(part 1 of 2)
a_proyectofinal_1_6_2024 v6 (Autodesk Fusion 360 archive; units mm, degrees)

design "a_proyectofinal_1_6_2024" references "nichrome wire", "LCD_grande", "a_supeior_finaldeproyecto_2024", "_dht22 aM2302.38a1238d-d74f-4ad3-8c3c-e908f9285f82", "VENTILADOR", "acentral_unido", "acentral_unido", "base1", "soporte_vidrio", "vidrio"
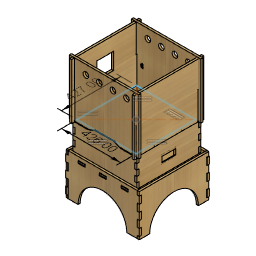
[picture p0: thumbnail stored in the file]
component_insert "Component Insert2"
component_insert "Component Insert3"
component_insert "Component Insert4"
component_insert "Component Insert5"
component_insert "Component Insert6"
position "Position1"
sketch "Sketch1" plane through (0, 0, 0) normal (0, 0, 1) x axis (1, 0, 0)
  line L1 (12, -36.5) -> (438, -36.5)
  line L2 (12, -463.5) -> (12, -36.5)
  line L3 (438, -463.5) -> (12, -463.5)
  line L4 (438, -36.5) -> (438, -463.5)
  line L5 (12, -463.5) -> (438, -36.5)
  line L6 (438, -463.5) -> (12, -36.5)
  point P6 (225, -250)
  point P4 (12, -463.5)
  point P5 (438, -463.5)
  point P3 (12, -36.5)
  horizontal L1
  perpendicular L1 L2
  parallel L1 L3
  parallel L2 L4
  coincident L5 P6
  coincident L6 P6
  dimension "d1" distance P4 P5 = 426
  dimension "d2" distance P3 P4 = 427
extrude "Extrude1" new body sketch "Sketch1" profile of L1 L2 L3 L4 along normal blind 3
sketch "Sketch2" plane through (0, 0, 3) normal (0, 0, 1) x axis (-1, 0, 0)
  line L1 (-438, 36.5) -> (-438, 463.5)
  line L2 (-12, 36.5) -> (-438, 36.5)
  line L3 (-12, 463.5) -> (-12, 36.5)
  line L4 (-438, 463.5) -> (-12, 463.5)
  circle C1 centre (-225, 250) radius 80
  dimension "d5" diameter C1 = 160
extrude "Extrude2" cut sketch "Sketch2" profile of C1 distance 5
sketch "Sketch3" plane through (0, 0, 3) normal (0, 0, 1) x axis (-1, 0, 0)
  line L1 (-438, 36.5) -> (-438, 463.5)
  line L2 (-12, 36.5) -> (-438, 36.5)
  line L3 (-12, 463.5) -> (-12, 36.5)
  line L4 (-438, 463.5) -> (-12, 463.5)
  circle C1 centre (-225, 250) radius 80
component_insert "Component Insert8"
component_insert "Component Insert9"
component_insert "Component Insert10"
component_insert "Component Insert11"
component_insert "Component Insert12"
component_insert "Component Insert13"
component_insert "Component Insert14"

design "b_superior_atras"
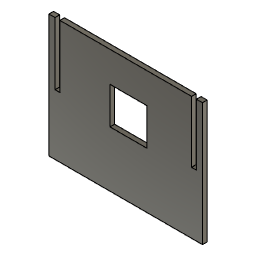
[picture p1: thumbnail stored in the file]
sketch "Sketch1" plane through (0, 0, 0) normal (0, 1, 0) x axis (1, 0, 0)
  line L1 (500, 0) -> (500, -400)
  line L2 (0, 0) -> (500, 0)
  line L3 (0, -400) -> (0, 0)
  line L4 (20, -400) -> (0, -400)
  line L5 (20, -200) -> (20, -400)
  line L6 (0, -400) -> (0, -200)
  line L7 (480, -400) -> (500, -400)
  line L8 (480, -200) -> (480, -400)
  line L9 (500, -400) -> (500, -200)
  line L10 (35.75, -196.5937) -> (35.75, -400)
  line L11 (20, -196.5937) -> (35.75, -196.5937)
  line L12 (20, -400) -> (20, -196.5937)
  line L13 (464.25, -200) -> (464.25, -400)
  line L14 (480, -200) -> (464.25, -200)
  line L15 (480, -400) -> (480, -200)
  line L16 (20, -400) -> (0, -400)
  line L17 (464.25, -400) -> (35.75, -400)
  line L18 (500, -400) -> (480, -400)
  point P2 (0, -400)
  point P3 (500, -400)
  point P5 (0, 0)
  point P6 (20, -400)
  point P8 (0, -200)
  point P9 (480, -400)
  point P11 (500, -200)
  point P12 (35.75, -400)
  point P15 (464.25, -400)
  horizontal L16
  vertical L1
  horizontal L2
  vertical L3
  horizontal L4
  vertical L5
  vertical L6
  horizontal L7
  vertical L8
  vertical L9
  vertical L10
  horizontal L11
  vertical L12
  vertical L13
  horizontal L14
  vertical L15
  collinear L16 L17
  collinear L17 L18
  dimension "d1" distance P2 P3 = 500
  dimension "d2" distance P2 P5 = 400
  dimension "d3" distance P2 P6 = 20
  dimension "d4" distance P2 P8 = 200
  dimension "d5" distance P3 P9 = 20
  dimension "d6" distance P3 P11 = 200
  dimension "d7" distance P6 P12 = 15.75
  dimension "d8" distance P9 P15 = 15.75
extrude "Extrude1" new body sketch "Sketch1" profile of L18 L1 L2 L3 L4 L5 L6 L7 L8 L9 L10 L11 L12 L13 L14 L15 along normal blind 15
sketch "Sketch2" plane through (0, 0, 0) normal (0, -1, 0) x axis (1, 0, 0)
  line L1 (35.75, 400) -> (464.25, 400)
  line L2 (35.75, 196.5937) -> (35.75, 400)
  line L3 (20, 196.5937) -> (35.75, 196.5937)
  line L4 (20, 400) -> (20, 196.5937)
  line L5 (0, 400) -> (20, 400)
  line L6 (0, 0) -> (0, 400)
  line L7 (500, 0) -> (0, 0)
  line L8 (500, 400) -> (500, 0)
  line L9 (480, 400) -> (500, 400)
  line L10 (480, 200) -> (480, 400)
  line L11 (464.25, 200) -> (480, 200)
  line L12 (464.25, 400) -> (464.25, 200)
  line L13 (318.7507, 301.2232) -> (198.7507, 301.2232)
  line L14 (318.7507, 181.2232) -> (318.7507, 301.2232)
  line L15 (198.7507, 181.2232) -> (318.7507, 181.2232)
  line L16 (198.7507, 301.2232) -> (198.7507, 181.2232)
  point P14 (198.7507, 301.2232)
  point P15 (318.7507, 301.2232)
  point P17 (198.7507, 181.2232)
  horizontal L13
  vertical L14
  horizontal L15
  vertical L16
  dimension "d12" distance P14 P15 = 120
  dimension "d13" distance P14 P17 = 120
extrude "Extrude2" cut sketch "Sketch2" profile of L13 L14 L15 L16 against normal blind 200

design "nichrome wire"
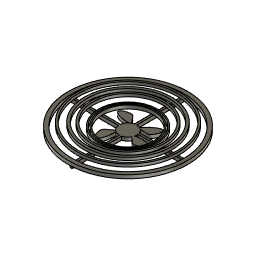
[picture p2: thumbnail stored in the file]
sketch "Sketch1" plane through (0, 0, 0) normal (0, 0, 1) x axis (1, 0, 0)
  curve K1 (6.0577, 10.9616) -> (6.0577, 10.9616)
  curve K2 (6.0577, 10.9616) -> (6.0577, 10.9616)
  curve K3 (6.0577, 10.9616) -> (6.0577, 10.9616)
  curve K4 (10.9382, -3.5735) -> (10.9382, -3.5735)
  curve K5 (10.9382, -3.5735) -> (10.9382, -3.5735)
  curve K6 (10.9382, -3.5735) -> (10.9382, -3.5735)
  curve K7 (-7.1676, 10.1341) -> (-7.1676, 10.1341)
  curve K8 (-7.1676, 10.1341) -> (-7.1676, 10.1341)
  curve K9 (-7.1676, 10.1341) -> (-7.1676, 10.1341)
  curve K10 (-7.2895, -9.5589) -> (-7.2895, -9.5589)
  curve K11 (-7.2895, -9.5589) -> (-7.2895, -9.5589)
  curve K12 (-7.2895, -9.5589) -> (-7.2895, -9.5589)
  circle C1 centre (0, 0) radius 12.5241
  point P1 (0, 0)
  point P2 (0, 0)
  point P4 (0, 0)
  point P5 (6.0577, 10.9616)
  coincident P1 P2
  coincident P1 P4
  coincident C1 P5
extrude "Extrude1" new body sketch "Sketch1" along normal blind 5
sketch "Sketch2" plane through (0, 0, 5) normal (0, 0, 1) x axis (-1, 0, 0)
  curve K1 (7.8082, -9.7921) -> (6.8465, -10.4871)
  curve K2 (6.8517, 10.4837) -> (8.5607, 9.1416)
  curve K3 (-12.2106, 2.7847) -> (-11.2008, 5.6031)
  curve K4 (-6.0577, -10.9616) -> (-8.1749, -9.4882)
  arc A1 centre (0, 0) radius 12.5241 clockwise from (6.8465, -10.4871) to (-6.0577, -10.9616)
  arc A2 centre (0, 0) radius 12.5241 clockwise from (8.5607, 9.1416) to (7.8082, -9.7921)
  arc A3 centre (0, 0) radius 12.5241 clockwise from (-11.2008, 5.6031) to (6.8517, 10.4837)
  arc A4 centre (0, 0) radius 12.5241 clockwise from (-8.1749, -9.4882) to (-12.2106, 2.7847)
  circle C1 centre (0, 0) radius 40.3113
  circle C2 centre (0, 0) radius 38.6887
  circle C3 centre (0, 0) radius 42.0472
  circle C4 centre (0, 0) radius 36.7361
  point P1 (0, 0)
  point P11 (0, 0)
  point P14 (0, 0)
  coincident P1 P11
  concentric C1 C2
  concentric C2 C3
  coincident P1 P14
extrude "Extrude2" new body sketch "Sketch2" profile of C1 C3 along normal blind 5
sketch "Sketch3" plane through (0, 0, 5) normal (0, 0, 1) x axis (-1, 0, 0)
  curve K1 (7.8082, -9.7921) -> (6.8465, -10.4871)
  curve K2 (6.8517, 10.4837) -> (8.5607, 9.1416)
  curve K3 (-12.2106, 2.7847) -> (-11.2008, 5.6031)
  curve K4 (-6.0577, -10.9616) -> (-8.1749, -9.4882)
  arc A1 centre (0, 0) radius 12.5241 clockwise from (6.8465, -10.4871) to (-6.0577, -10.9616)
  arc A2 centre (0, 0) radius 12.5241 clockwise from (8.5607, 9.1416) to (7.8082, -9.7921)
  arc A3 centre (0, 0) radius 12.5241 clockwise from (-11.2008, 5.6031) to (6.8517, 10.4837)
  arc A4 centre (0, 0) radius 12.5241 clockwise from (-8.1749, -9.4882) to (-12.2106, 2.7847)
  circle C1 centre (0, 0) radius 38.5442
  circle C2 centre (0, 0) radius 36.8118
  point P1 (0, 0)
  point P11 (0, 0)
  point P12 (0, 0)
  coincident P1 P11
  coincident P1 P12
extrude "Extrude3" new body sketch "Sketch3" profile of C1 C2 along normal blind 5
sketch "Sketch4" plane through (0, 0, 10) normal (0, 0, 1) x axis (-1, 0, 0)
  line L1 (-79.5893, -78.0883) -> (80.4107, -78.0883)
  line L2 (-79.5893, 81.9117) -> (-79.5893, -78.0883)
  line L3 (80.4107, 81.9117) -> (-79.5893, 81.9117)
  line L4 (80.4107, -78.0883) -> (80.4107, 81.9117)
  circle C1 centre (0, 0) radius 36.8118
  circle C2 centre (0, 0) radius 38.5442
  circle C3 centre (0, 0) radius 52.582
  circle C4 centre (0, 0) radius 49.7551
  circle C5 centre (0, 0) radius 61.9417
  circle C6 centre (0, 0) radius 58.3666
  circle C7 centre (0, 0) radius 73.4024
  circle C8 centre (0, 0) radius 70.7107
  point P1 (0, 0)
  point P9 (0, 0)
  point P10 (0, 0)
  point P3 (80.4107, -78.0883)
  point P4 (-79.5893, -78.0883)
  point P6 (80.4107, 81.9117)
  horizontal L1
  vertical L2
  horizontal L3
  vertical L4
  concentric C1 C3
  concentric C3 C4
  coincident P1 P9
  coincident P1 P10
  concentric C3 C7
  concentric C3 C8
  dimension "d9" distance P3 P4 = 160
  dimension "d10" distance P3 P6 = 160
extrude "Extrude4" new body sketch "Sketch4" profile of C3 C4 C5 C6 C7 C8 along normal blind 5
sketch "Sketch5" plane through (0, 0, 5) normal (0, 0, 1) x axis (-1, 0, 0)
  curve K1 (7.8082, -9.7921) -> (6.8465, -10.4871)
  curve K2 (6.8517, 10.4837) -> (8.5607, 9.1416)
  curve K3 (-12.2106, 2.7847) -> (-11.2008, 5.6031)
  curve K4 (-6.0577, -10.9616) -> (-8.1749, -9.4882)
  arc A1 centre (0, 0) radius 12.5241 clockwise from (6.8465, -10.4871) to (-6.0577, -10.9616)
  arc A2 centre (0, 0) radius 12.5241 clockwise from (8.5607, 9.1416) to (7.8082, -9.7921)
  arc A3 centre (0, 0) radius 12.5241 clockwise from (-11.2008, 5.6031) to (6.8517, 10.4837)
  arc A4 centre (0, 0) radius 12.5241 clockwise from (-8.1749, -9.4882) to (-12.2106, 2.7847)
  circle C1 centre (0, 0) radius 80
  circle C2 centre (0, 0) radius 85.3902
  point P1 (0, 0)
  point P11 (0, 0)
  coincident P1 P11
  concentric C1 C2
  dimension "d13" diameter C1 = 160
extrude "Extrude5" new body sketch "Sketch5" profile of C1 C2 along normal blind 5
sketch "Sketch6" plane through (0, 0, 0) normal (0, 0, 1) x axis (1, 0, 0)
  line L1 (-0.0367, 11.7312) -> (-3.0367, 11.7312)
  line L2 (-0.0367, 81.7312) -> (-0.0367, 11.7312)
  line L3 (-3.0367, 81.7312) -> (-0.0367, 81.7312)
  line L4 (-3.0367, 11.7312) -> (-3.0367, 81.7312)
  line L5 (80, 4.7468) -> (8.1991, 4.7468)
  line L6 (80, 1.7468) -> (80, 4.7468)
  line L7 (8.1991, 1.7468) -> (80, 1.7468)
  line L8 (8.1991, 4.7468) -> (8.1991, 1.7468)
  line L9 (-82.2947, 1.7468) -> (-11.8432, 1.7468)
  line L10 (-82.2947, -1.2532) -> (-82.2947, 1.7468)
  line L11 (-11.8432, -1.2532) -> (-82.2947, -1.2532)
  line L12 (-11.8432, 1.7468) -> (-11.8432, -1.2532)
  line L13 (3, -10) -> (0, -10)
  line L14 (3, -82.7103) -> (3, -10)
  line L15 (0, -82.7103) -> (3, -82.7103)
  line L16 (0, -10) -> (0, -82.7103)
  point P2 (-3.0367, 11.7312)
  point P3 (-0.0367, 11.7312)
  point P5 (-3.0367, 81.7312)
  point P6 (8.1991, 4.7468)
  point P9 (8.1991, 1.7468)
  point P10 (-11.8432, 1.7468)
  point P13 (-11.8432, -1.2532)
  point P14 (0, -10)
  point P15 (3, -10)
  horizontal L1
  vertical L2
  horizontal L3
  vertical L4
  horizontal L5
  vertical L6
  horizontal L7
  vertical L8
  horizontal L9
  vertical L10
  horizontal L11
  vertical L12
  horizontal L13
  vertical L14
  horizontal L15
  vertical L16
  dimension "d16" distance P2 P3 = 3
  dimension "d17" distance P2 P5 = 70
  dimension "d18" distance P6 P9 = 3
  dimension "d19" distance P10 P13 = 3
  dimension "d20" distance P14 P15 = 3
extrude "Extrude6" add sketch "Sketch6" along normal blind 5
sketch "Sketch7" plane through (0, 0, 10) normal (0, 0, 1) x axis (-1, 0, 0)
  curve K1 (5.1073, -102.997) -> (5.1073, -102.997)
  circle C1 centre (0, 0) radius 36.8118
  circle C2 centre (0, 0) radius 38.5442
extrude "Extrude7" cut sketch "Sketch7" profile of C2 K1 along normal blind 1

design "a_centro_atras"
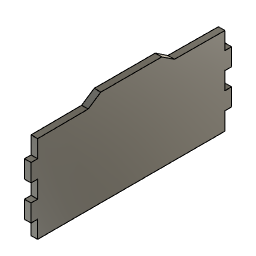
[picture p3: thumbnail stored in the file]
sketch "Sketch1" plane through (0, 0, 0) normal (1, 0, 0) x axis (0, 1, 0)
  line L1 (300, 220) -> (160, 220)
  line L2 (15, 0) -> (444.8, 0)
  line L3 (300, 220) -> (230, 220)
  line L4 (160, 220) -> (230, 220)
  line L5 (328.7889, 200.8074) -> (300, 220)
  line L6 (131.2111, 200.8074) -> (160, 220)
  line L7 (15.2, 160.15) -> (15.2, 200)
  line L8 (0, 160.15) -> (15.2, 160.15)
  line L9 (0, 119.6381) -> (15.2, 119.6381)
  line L10 (15.2, 79.7881) -> (0, 79.7881)
  line L11 (15.2, 119.6381) -> (15.2, 79.7881)
  line L12 (444.8, 160.15) -> (460, 160.15)
  line L13 (460, 120.3) -> (444.8, 120.3)
  line L14 (460, 160.15) -> (460, 120.3)
  line L15 (444.8, 160.15) -> (444.8, 200)
  line L16 (460, 160.15) -> (444.8, 160.15)
  line L17 (444.8, 120.3) -> (460, 120.3)
  line L18 (444.8, 80.45) -> (444.8, 120.3)
  line L19 (460, 80.45) -> (444.8, 80.45)
  line L20 (444.8, 200) -> (328.7889, 200.8074)
  line L21 (460, 120.3) -> (460, 160.15)
  line L22 (460, 40.6) -> (460, 80.45)
  line L23 (15.2, 160.15) -> (15.2, 200)
  line L24 (0, 160.15) -> (15.2, 160.15)
  line L25 (0, 79.7881) -> (0, 39.894)
  line L26 (0, 160.15) -> (0, 119.6381)
  line L27 (15, 39.894) -> (0, 39.894)
  line L28 (15, 0) -> (15, 39.894)
  line L29 (0, 0) -> (15, 0)
  line L30 (444.8, 80.45) -> (460, 80.45)
  line L31 (460, 40.6) -> (444.8, 40.6)
  line L32 (460, 80.45) -> (460, 40.6)
  line L33 (460, 40.6) -> (444.8, 40.6)
  line L34 (444.8, 40.6) -> (444.8, 0)
  line L35 (131.2111, 200.8074) -> (15.2, 200)
  point P2 (230, 220)
  point P3 (300, 220)
  point P4 (160, 220)
  point P5 (328.7889, 200.8074)
  point P6 (131.2111, 200.8074)
  point P10 (15.2, 119.6381)
  point P13 (15.2, 79.7881)
  point P14 (460, 160.15)
  point P15 (444.8, 160.15)
  point P17 (460, 120.3)
  point P22 (460, 80.45)
  point P29 (444.8, 80.45)
  point P31 (460, 40.6)
  horizontal L1
  horizontal L2
  vertical L25
  vertical L7
  horizontal L8
  horizontal L9
  horizontal L10
  vertical L11
  horizontal L12
  horizontal L13
  vertical L14
  vertical L15
  horizontal L16
  horizontal L17
  vertical L18
  horizontal L19
  coincident L1 P2
  collinear L21 L22
  vertical L23
  horizontal L24
  collinear L25 L26
  horizontal L27
  vertical L28
  horizontal L29
  horizontal L30
  horizontal L31
  vertical L32
  horizontal L33
  vertical L34
  dimension "d2" distance P2 P3 = 70
  dimension "d3" distance P2 P4 = 70
  dimension "d5" distance P3 P5 = 34.6
  dimension "d6" distance P4 P6 = 34.6
  dimension "d10" distance P10 P13 = 39.85
  dimension "d11" distance P14 P15 = 15.2
  dimension "d14" distance P17 P22 = 39.85
  dimension "d15" distance P22 P29 = 15.2
  dimension "d16" distance P22 P31 = 39.85
extrude "Extrude1" new body sketch "Sketch1" profile of L1 L22 L2 L26 L3 L4 L5 L6 L7 L8 L9 L10 L11 L12 L13 L14 L15 L16 L17 L18 L19 L20 L23 L24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 along normal blind 15

design "base1" references "lateralD_projectfinal", "lateralIzq_projectfinal", "lateralAdelante_projectfinal", "lateral_Atras_projectfinal", "base1_porjectfinal"
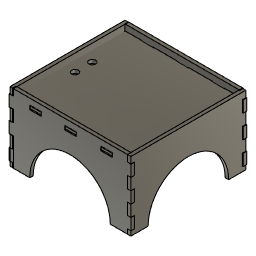
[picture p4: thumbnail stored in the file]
component_insert "Component Insert1"
component_insert "Component Insert2"
component_insert "Component Insert3"
component_insert "Component Insert4"
component_insert "Component Insert5"

design "base1_porjectfinal"
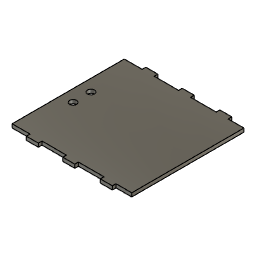
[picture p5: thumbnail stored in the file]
sketch "Sketch1" plane through (0, 0, 0) normal (0, 0, 1) x axis (1, 0, 0)
  line L1 (-500, 469) -> (-500, 0)
  line L2 (0, 0) -> (0, 469)
  line L3 (-375.3783, 484.2) -> (-375.3783, 469)
  line L4 (-425.3783, 484.2) -> (-375.3783, 484.2)
  line L5 (-425.3783, 469) -> (-425.3783, 484.2)
  line L6 (-425.3783, 484.2) -> (-375.0283, 484.2)
  line L7 (-223.1255, 484.2) -> (-223.1255, 469)
  line L8 (-273.1255, 484.2) -> (-223.1255, 484.2)
  line L9 (-273.1255, 469) -> (-273.1255, 484.2)
  line L10 (-115.7395, 484.2) -> (-115.7395, 469)
  line L11 (-65.7395, 484.2) -> (-115.7395, 484.2)
  line L12 (-65.7395, 469) -> (-65.7395, 484.2)
  line L13 (-115.7395, -15.2) -> (-65.7395, -15.2)
  line L14 (-272.7755, -15.2) -> (-272.7755, 0)
  line L15 (-115.7395, 0) -> (-115.7395, -15.2)
  line L16 (-375.0283, -15.2) -> (-425.0283, -15.2)
  line L17 (-222.7755, 0) -> (-222.7755, -15.2)
  line L18 (-425.0283, -15.2) -> (-425.0283, 0)
  line L19 (-65.7395, -15.2) -> (-65.7395, 0)
  line L20 (-375.0283, 0) -> (-375.0283, -15.2)
  line L21 (-222.7755, -15.2) -> (-272.7755, -15.2)
  line L22 (-425.3783, 469) -> (-500, 469)
  line L23 (-273.1255, 469) -> (-375.3783, 469)
  line L24 (-115.7395, 469) -> (-223.1255, 469)
  line L25 (0, 469) -> (-65.7395, 469)
  line L26 (-500, 0) -> (-425.3783, 0)
  line L27 (-375.0283, 0) -> (-272.7755, 0)
  line L28 (-65.7395, 0) -> (0, 0)
  line L29 (-222.7755, 0) -> (-115.7395, 0)
  point P1 (0, 0)
  point P2 (0, 0)
  point P12 (-273.1255, 469)
  point P16 (-65.7395, 469)
  point P3 (-500, 0)
  point P5 (0, 469)
  point P6 (-425.3783, 469)
  point P7 (-375.3783, 469)
  point P9 (-425.3783, 484.2)
  point P13 (-223.1255, 469)
  point P15 (-273.1255, 484.2)
  point P17 (-115.7395, 469)
  point P19 (-65.7395, 484.2)
  point P27 (-375.0283, -15.2)
  point P28 (-425.0283, -15.2)
  point P26 (-425.0283, 0)
  point P30 (-222.7755, -15.2)
  point P31 (-272.7755, -15.2)
  point P33 (-272.7755, 0)
  point P22 (-65.7395, -15.2)
  point P25 (-115.7395, -15.2)
  point P23 (-65.7395, 0)
  horizontal L28
  vertical L1
  horizontal L22
  vertical L2
  coincident P1 P2
  vertical L3
  horizontal L4
  vertical L5
  horizontal L6
  vertical L7
  horizontal L8
  vertical L9
  coincident P12 L22
  vertical L10
  horizontal L11
  vertical L12
  coincident P16 L22
  horizontal L16
  vertical L20
  vertical L18
  horizontal L21
  vertical L17
  vertical L14
  horizontal L13
  vertical L15
  vertical L19
  collinear L22 L23
  collinear L23 L24
  collinear L24 L25
  collinear L26 L28
  collinear L27 L28
  collinear L28 L29
  dimension "d1" distance P2 P3 = 500
  dimension "d2" distance P2 P5 = 469
  dimension "d3" distance P6 P7 = 50
  dimension "d4" distance P6 P9 = 15.2
  dimension "d5" distance P12 P13 = 50
  dimension "d6" distance P12 P15 = 15.2
  dimension "d7" distance P16 P17 = 50
  dimension "d8" distance P16 P19 = 15.2
  dimension "d9" distance P27 P28 = 50
  dimension "d10" distance P26 P28 = 15.2
  dimension "d11" distance P30 P31 = 50
  dimension "d12" distance P31 P33 = 15.2
  dimension "d13" distance P22 P25 = 50
  dimension "d14" distance P22 P23 = 15.2
extrude "Extrude1" new body sketch "Sketch1" profile of L29 L1 L25 L2 L3 L4 L5 L6 L7 L8 L9 L10 L11 L12 L13 L14 L15 L16 L17 L18 L19 L20 L21 along normal blind 15
sketch "Sketch2" plane through (0, 0, 0) normal (0, 0, 1) x axis (1, 0, 0)
  circle C1 centre (-450, 280) radius 20
  circle C2 centre (-450, 205) radius 20
  dimension "d17" diameter C1 = 40
  dimension "d18" diameter C2 = 40
hole "Hole1" HoleDepth 29 HoleDiameter 29 TipAngle 118

design "b_superior_lado izquierdo-d"
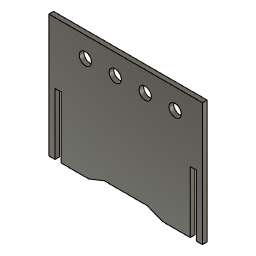
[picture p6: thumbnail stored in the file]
sketch "Sketch1" plane through (0, 0, 0) normal (0, 1, 0) x axis (1, 0, 0)
  line L1 (500, -400) -> (500, 0)
  line L2 (0, -400) -> (500, -400)
  line L3 (0, 0) -> (0, -400)
  line L4 (320, -20) -> (250, -20)
  line L5 (180, -20) -> (250, -20)
  line L6 (370.02, 0) -> (460, 0)
  line L7 (180, -20) -> (129.98, 0)
  line L8 (370.02, 0) -> (320, -20)
  line L9 (129.98, 0) -> (20, 0)
  line L10 (20, -200) -> (20, 0)
  line L11 (480, -200) -> (480, 0)
  line L12 (40, -200) -> (40, 0)
  line L13 (20, -200) -> (40, -200)
  line L14 (20, 0) -> (20, -200)
  line L15 (460, -200) -> (460, 0)
  line L16 (480, -200) -> (460, -200)
  line L17 (480, 0) -> (480, -200)
  line L18 (20, 0) -> (0, 0)
  line L19 (480, 0) -> (500, 0)
  point P1 (0, 0)
  point P2 (0, 0)
  point P22 (0, 0)
  point P5 (0, -400)
  point P6 (20, 0)
  point P11 (129.98, 0)
  point P14 (20, -200)
  point P13 (480, 0)
  point P15 (480, -200)
  point P18 (20, -200)
  point P7 (480, 0)
  point P21 (480, -200)
  vertical L1
  horizontal L2
  vertical L3
  coincident P1 P2
  vertical L12
  horizontal L13
  vertical L14
  vertical L15
  horizontal L16
  vertical L17
  coincident P1 P22
  perpendicular L14 L18
  perpendicular L11 L19
  dimension "d2" distance P2 P5 = 400
  dimension "d8" distance P6 P11 = 109.98
  dimension "d11" distance P6 P14 = 200
  dimension "d12" distance P13 P15 = 200
  dimension "d14" distance P6 P18 = 200
  dimension "d16" distance P7 P21 = 200
extrude "Extrude1" new body sketch "Sketch1" along normal blind 15
sketch "Sketch2" plane through (0, 0, 0) normal (0, -1, 0) x axis (1, 0, 0)
  line L1 (500, 400) -> (500, 0)
  line L2 (0, 400) -> (500, 400)
  line L3 (0, 0) -> (0, 400)
  line L4 (20, 0) -> (0, 0)
  line L5 (20, 200) -> (20, 0)
  line L6 (40, 200) -> (20, 200)
  line L7 (40, 0) -> (40, 200)
  line L8 (129.98, 0) -> (40, 0)
  line L9 (180, 20) -> (129.98, 0)
  line L10 (320, 20) -> (180, 20)
  line L11 (370.02, 0) -> (320, 20)
  line L12 (460, 0) -> (370.02, 0)
  line L13 (460, 200) -> (460, 0)
  line L14 (480, 200) -> (460, 200)
  line L15 (480, 0) -> (480, 200)
  line L16 (500, 0) -> (480, 0)
  line L17 (118.9633, 333.53) -> (118.75, 333.53)
  circle C1 centre (118.75, 333.53) radius 20
  circle C2 centre (215.9, 333.53) radius 20
  circle C3 centre (313.41, 333.53) radius 20
  circle C4 centre (410.92, 333.53) radius 20
  point P19 (118.75, 333.53)
  point P20 (118.75, 333.53)
  point P21 (215.9, 333.53)
  point P22 (313.41, 333.53)
  point P23 (410.92, 333.53)
  coincident P19 P20
  dimension "d21" diameter C1 = 40
  dimension "d22" distance P20 P21 = 97.15
  dimension "d23" diameter C2 = 40
  dimension "d24" distance P21 P22 = 97.51
  dimension "d25" diameter C3 = 40
  dimension "d26" distance P22 P23 = 97.51
  dimension "d27" diameter C4 = 40
extrude "Extrude2" cut sketch "Sketch2" profile of C1 C2 C3 C4 distance 20

design "lateral_Atras_projectfinal" references "lateralD_projectfinal"
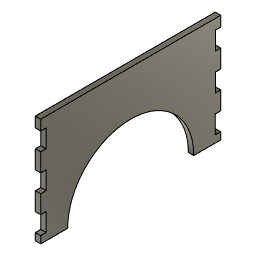
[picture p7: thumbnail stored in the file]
sketch "Sketch1" plane through (0, 0, 0) normal (1, 0, 0) x axis (0, 1, 0)
  line L1 (500, 0) -> (0, 0)
  line L2 (0, -28.51) -> (0, 0)
  line L3 (15.2, -28.51) -> (0, -28.51)
  line L4 (15.2, -78.86) -> (15.2, -28.51)
  line L5 (0, -78.86) -> (15.2, -78.86)
  line L6 (15.2, -129.21) -> (0, -129.21)
  line L7 (15.2, -179.56) -> (15.2, -129.21)
  line L8 (15.2, -179.56) -> (0, -179.56)
  line L9 (485.5177, -179.56) -> (500.7177, -179.56)
  line L10 (485.5177, -28.51) -> (485.5177, -78.86)
  line L11 (500.7177, -28.51) -> (485.5177, -28.51)
  line L12 (485.5177, -129.21) -> (485.5177, -179.56)
  line L13 (485.5177, -78.86) -> (500.7177, -78.86)
  line L14 (500.7177, -129.21) -> (485.5177, -129.21)
  line L15 (0, -129.21) -> (0, -78.86)
  line L16 (500, -28.51) -> (500, 0)
  line L17 (500, -129.21) -> (500, -78.86)
  line L18 (75, -300) -> (0, -300)
  line L19 (500, -300) -> (425, -300)
  line L20 (15.2, -179.56) -> (0, -179.56)
  line L21 (15.2, -229.91) -> (0, -229.91)
  line L22 (15.2, -280.26) -> (15.2, -229.91)
  line L23 (0, -280.26) -> (15.2, -280.26)
  line L24 (0, -229.91) -> (0, -179.56)
  line L25 (0, -300) -> (0, -280.26)
  line L26 (484.8, -179.56) -> (500, -179.56)
  line L27 (500, -229.91) -> (484.8, -229.91)
  line L28 (484.8, -280.26) -> (500.3, -280.26)
  line L29 (484.8, -229.91) -> (484.8, -280.26)
  line L30 (500, -229.91) -> (500, -179.56)
  line L31 (500, -300) -> (500, -280.26)
  arc A1 centre (250, -300) radius 175 clockwise from (75, -300) to (425, -300)
  point P1 (0, 0)
  point P2 (0, 0)
  point P6 (0, 0)
  point P24 (500, -129.21)
  point P25 (500, -179.56)
  point P26 (500, -28.51)
  point P27 (500, -78.86)
  point P30 (425, -300)
  point P28 (250, -300)
  point P41 (500, -280.26)
  point P3 (500, 0)
  point P5 (0, -300)
  point P7 (0, -28.51)
  point P8 (15.2, -28.51)
  point P10 (0, -78.86)
  point P11 (0, -129.21)
  point P14 (0, -179.56)
  point P15 (15.2, -179.56)
  point P19 (485.5177, -28.51)
  point P20 (500.7177, -28.51)
  point P21 (485.5177, -78.86)
  point P18 (485.5177, -179.56)
  point P23 (485.5177, -129.21)
  point P31 (15.2, -179.56)
  point P32 (0, -229.91)
  point P33 (15.2, -229.91)
  point P35 (0, -280.26)
  point P36 (484.8, -179.56)
  point P38 (500, -229.91)
  point P37 (484.8, -229.91)
  point P40 (484.8, -280.26)
  horizontal L1
  vertical L16
  coincident P1 P2
  coincident P1 P6
  perpendicular L1 L2
  horizontal L3
  vertical L4
  horizontal L5
  horizontal L6
  vertical L7
  horizontal L8
  horizontal L11
  horizontal L13
  vertical L10
  horizontal L14
  horizontal L9
  vertical L12
  collinear L15 L24
  coincident L14 P24
  coincident L9 P25
  collinear L16 L30
  coincident L11 P26
  coincident L13 P27
  collinear L16 L17
  perpendicular L18 L30
  coincident P30 L18
  collinear L18 L19
  coincident P28 L18
  horizontal L20
  horizontal L21
  vertical L22
  horizontal L23
  collinear L24 L25
  horizontal L26
  horizontal L27
  horizontal L28
  vertical L29
  coincident L28 P41
  collinear L30 L31
  dimension "d1" distance P2 P3 = 500
  dimension "d2" distance P2 P5 = 300
  dimension "d4" distance P6 P7 = 28.51
  dimension "d5" distance P7 P8 = 15.2
  dimension "d6" distance P7 P10 = 50.35
  dimension "d10" distance P11 P14 = 50.35
  dimension "d11" distance P14 P15 = 15.2
  dimension "d13" distance P19 P20 = 15.2
  dimension "d14" distance P19 P21 = 50.35
  dimension "d15" distance P18 P23 = 50.35
  dimension "d23" diameter A1 = 350
  dimension "d24" distance P14 P31 = 15.2
  dimension "d25" distance P14 P32 = 50.35
  dimension "d26" distance P32 P33 = 15.2
  dimension "d27" distance P32 P35 = 50.35
  dimension "d28" distance P25 P36 = 15.2
  dimension "d29" distance P25 P38 = 50.35
  dimension "d31" distance P37 P40 = 50.35
extrude "Extrude1" new body sketch "Sketch1" profile of L1 L31 L2 L3 L4 L5 L6 L7 L8 L25 L9 L10 L11 L12 L13 L14 along normal blind 15
component_insert "Component Insert"

design "b_superior_adelente"
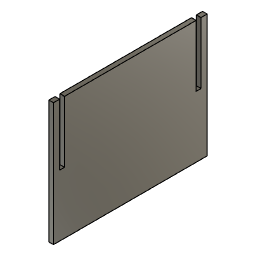
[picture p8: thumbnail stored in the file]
sketch "Sketch1" plane through (0, 0, 0) normal (1, 0, 0) x axis (0, 1, 0)
  line L1 (-483.5185, 0) -> (-483.5185, 400)
  line L2 (16.4815, 0) -> (-483.5185, 0)
  line L3 (16.4815, 400) -> (16.4815, 0)
  line L4 (-19.2685, 200) -> (-19.2685, 400)
  line L5 (-3.5185, 200) -> (-19.2685, 200)
  line L6 (-3.5185, 400) -> (-3.5185, 200)
  line L7 (-463.5185, 400) -> (-483.5185, 400)
  line L8 (-463.5185, 200) -> (-463.5185, 400)
  line L9 (-483.5185, 400) -> (-483.5185, 200)
  line L10 (-447.7685, 200) -> (-463.5185, 200)
  line L11 (-447.7685, 400) -> (-447.7685, 200)
  line L12 (-463.5185, 200) -> (-463.5185, 400)
  line L13 (-483.5185, 400) -> (-463.5185, 400)
  line L14 (-3.5185, 400) -> (16.4815, 400)
  line L15 (-447.7685, 400) -> (-19.2685, 400)
  point P2 (16.4815, 400)
  point P3 (-483.5185, 400)
  point P5 (16.4815, 0)
  point P6 (-3.5185, 400)
  point P7 (-19.2685, 400)
  point P9 (-3.5185, 200)
  point P10 (-463.5185, 400)
  point P12 (-483.5185, 200)
  point P11 (-463.5185, 200)
  point P13 (-447.7685, 200)
  point P15 (-463.5185, 400)
  horizontal L14
  vertical L1
  horizontal L2
  vertical L3
  vertical L4
  horizontal L5
  vertical L6
  horizontal L7
  vertical L8
  vertical L9
  horizontal L10
  vertical L11
  vertical L12
  collinear L13 L14
  collinear L14 L15
  dimension "d1" distance P2 P3 = 500
  dimension "d2" distance P2 P5 = 400
  dimension "d3" distance P6 P7 = 15.75
  dimension "d4" distance P6 P9 = 200
  dimension "d5" distance P3 P10 = 20
  dimension "d6" distance P3 P12 = 200
  dimension "d7" distance P11 P13 = 15.75
  dimension "d8" distance P11 P15 = 200
  dimension "d9" distance P2 P6 = 20
extrude "Extrude1" new body sketch "Sketch1" profile of L15 L1 L2 L3 L4 L5 L6 L7 L8 L9 L10 L11 L12 along normal blind 15

design "lateralD_projectfinal"
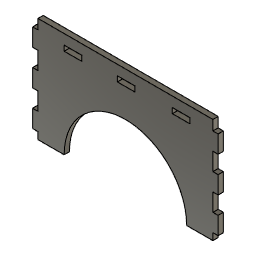
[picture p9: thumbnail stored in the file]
sketch "Sketch1" plane through (0, 0, 0) normal (0, 1, 0) x axis (1, 0, 0)
  line L1 (0, 0) -> (-500, 0)
  line L2 (-374.65, 28.51) -> (-425, 28.51)
  line L3 (-374.65, 43.71) -> (-374.65, 28.51)
  line L4 (-425, 43.71) -> (-374.65, 43.71)
  line L5 (-425, 28.51) -> (-425, 43.71)
  line L6 (-273.1255, 28.51) -> (-273.1255, 43.71)
  line L7 (-222.7755, 28.51) -> (-273.1255, 28.51)
  line L8 (-273.1255, 43.71) -> (-222.7755, 43.71)
  line L9 (-222.7755, 43.71) -> (-222.7755, 28.51)
  line L10 (-65.7396, 28.51) -> (-116.0896, 28.51)
  line L11 (-65.7396, 43.71) -> (-65.7396, 28.51)
  line L12 (-116.0896, 43.71) -> (-65.7396, 43.71)
  line L13 (-116.0896, 28.51) -> (-116.0896, 43.71)
  line L14 (-75, 300) -> (0, 300)
  line L15 (-500, 300) -> (-425, 300)
  line L16 (-500, 28.51) -> (-500, 0)
  line L17 (-515.2, 28.51) -> (-500, 28.51)
  line L18 (-515.2, 78.86) -> (-515.2, 28.51)
  line L19 (-515.2, 78.86) -> (-500, 78.86)
  line L20 (-500, 129.21) -> (-515.2, 129.21)
  line L21 (-500, 129.21) -> (-515.2, 129.21)
  line L22 (-515.2, 179.56) -> (-500, 179.56)
  line L23 (-515.2, 129.21) -> (-515.2, 179.56)
  line L24 (-500, 229.91) -> (-515.2, 229.91)
  line L25 (-515.2, 280.26) -> (-500, 280.26)
  line L26 (-515.2, 229.91) -> (-515.2, 280.26)
  line L27 (-0.2, 179.56) -> (15, 179.56)
  line L28 (15, 28.51) -> (15, 78.86)
  line L29 (-0.2, 78.86) -> (15, 78.86)
  line L30 (15, 129.21) -> (-0.2, 129.21)
  line L31 (15, 229.91) -> (-0.2, 229.91)
  line L32 (15, 280.26) -> (15, 229.91)
  line L33 (15, 129.21) -> (-0.2, 129.21)
  line L34 (-0.2, 28.51) -> (15, 28.51)
  line L35 (15, 179.56) -> (15, 129.21)
  line L36 (-0.2, 280.26) -> (15, 280.26)
  line L37 (-500, 0) -> (-500, 28.51)
  line L38 (-500, 78.86) -> (-500, 129.21)
  line L39 (0, 300) -> (0, 280.26)
  line L40 (0, 28.51) -> (0, 0)
  line L41 (-500, 280.26) -> (-500, 300)
  line L42 (-500, 179.56) -> (-500, 229.91)
  line L43 (0, 129.21) -> (0, 78.86)
  line L44 (0, 229.91) -> (0, 179.56)
  arc A1 centre (-250, 300) radius 175 clockwise from (-75, 300) to (-425, 300)
  point P6 (-250, 300)
  point P48 (0, 229.91)
  point P49 (0, 280.26)
  point P50 (0, 28.51)
  point P51 (0, 78.86)
  point P52 (0, 129.21)
  point P53 (0, 179.56)
  point P2 (-500, 0)
  point P5 (-500, 300)
  point P7 (-425, 28.51)
  point P8 (-374.65, 28.51)
  point P10 (-425, 43.71)
  point P11 (-273.1255, 28.51)
  point P12 (-222.7755, 28.51)
  point P14 (-273.1255, 43.71)
  point P15 (-116.0896, 28.51)
  point P16 (-65.7396, 28.51)
  point P18 (-116.0896, 43.71)
  point P21 (-500, 28.51)
  point P22 (-515.2, 28.51)
  point P24 (-500, 78.86)
  point P25 (-515.2, 78.86)
  point P27 (-500, 129.21)
  point P26 (-515.2, 129.21)
  point P30 (-515.2, 179.56)
  point P31 (-515.2, 229.91)
  point P32 (-500, 229.91)
  point P34 (-515.2, 280.26)
  horizontal L1
  vertical L40
  horizontal L14
  vertical L41
  horizontal L2
  vertical L3
  horizontal L4
  vertical L5
  horizontal L7
  vertical L9
  horizontal L8
  vertical L6
  horizontal L10
  vertical L11
  horizontal L12
  vertical L13
  collinear L14 L15
  coincident P6 L14
  perpendicular L1 L16
  horizontal L17
  vertical L18
  horizontal L19
  horizontal L20
  horizontal L21
  horizontal L22
  vertical L23
  horizontal L24
  horizontal L25
  vertical L26
  horizontal L34
  vertical L28
  horizontal L29
  horizontal L33
  horizontal L30
  vertical L35
  horizontal L27
  horizontal L31
  vertical L32
  horizontal L36
  collinear L37 L41
  collinear L38 L41
  coincident L31 P48
  coincident L36 P49
  collinear L39 L40
  coincident L34 P50
  coincident L29 P51
  collinear L40 L43
  collinear L41 L42
  coincident L30 P52
  coincident L27 P53
  collinear L43 L44
  dimension "d1" distance P2 P5 = 300
  dimension "d3" distance P7 P8 = 50.35
  dimension "d4" distance P7 P10 = 15.2
  dimension "d6" distance P11 P12 = 50.35
  dimension "d7" distance P11 P14 = 15.2
  dimension "d9" distance P15 P16 = 50.35
  dimension "d10" distance P15 P18 = 15.2
  dimension "d13" distance P2 P21 = 28.51
  dimension "d14" distance P21 P22 = 15.2
  dimension "d15" distance P21 P24 = 50.35
  dimension "d16" distance P24 P25 = 15.2
  dimension "d17" distance P24 P27 = 50.35
  dimension "d19" distance P26 P30 = 50.35
  dimension "d21" distance P30 P31 = 50.35
  dimension "d22" distance P31 P32 = 15.2
  dimension "d23" distance P31 P34 = 50.35
extrude "Extrude1" new body sketch "Sketch1" profile of L1 L44 L15 L42 A1 L2 L3 L4 L5 L6 L7 L8 L9 L10 L11 L12 L13 along normal blind 15

design "a_supeior_finaldeproyecto_2024" references "b_superior_lado izquierdo-d", "b_superior_atras", "b_superior_adelente"
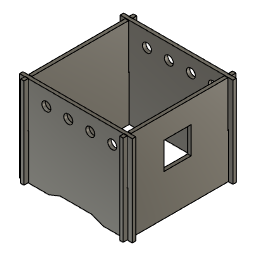
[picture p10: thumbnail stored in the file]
component_insert "Component Insert1"
component_insert "Component Insert2"
component_insert "Component Insert3"
component_insert "Component Insert4"

design "a_medioLateralIZQ"
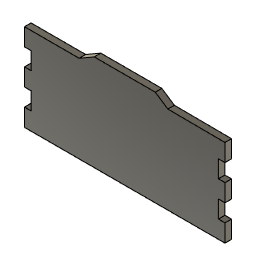
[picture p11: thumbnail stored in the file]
sketch "Sketch1" plane through (0, 0, 0) normal (0, 1, 0) x axis (1, 0, 0)
  line L1 (460, 0) -> (0, 0)
  line L2 (0, -200) -> (125.4, -200)
  line L3 (160, -220) -> (125.4, -200)
  line L4 (328.7889, -200.8074) -> (300, -220)
  line L5 (460, -160) -> (460, -200)
  line L6 (444.8, -160) -> (460, -160)
  line L7 (444.8, -120.15) -> (444.8, -160)
  line L8 (460, -120.15) -> (444.8, -120.15)
  line L9 (444.8, -80.15) -> (460, -80.15)
  line L10 (444.8, -40.3) -> (444.8, -80.15)
  line L11 (460, -40.3) -> (444.8, -40.3)
  line L12 (15.2, -160) -> (0, -160)
  line L13 (15.2, -120.15) -> (15.2, -160)
  line L14 (0, -120.15) -> (15.2, -120.15)
  line L15 (15.2, -80.15) -> (0, -80.15)
  line L16 (15.2, -40.3) -> (15.2, -80.15)
  line L17 (0, -40.3) -> (15.2, -40.3)
  line L18 (460, -200) -> (328.7889, -200.8074)
  line L19 (460, -200) -> (460, -160)
  line L20 (460, -40.3) -> (460, 0)
  line L21 (460, -120.15) -> (460, -80.15)
  line L22 (0, 0) -> (0, -40.3)
  line L23 (0, -160) -> (0, -200)
  line L24 (0, -80.15) -> (0, -120.15)
  line L25 (300, -220) -> (160, -220)
  point P1 (0, 0)
  point P2 (0, 0)
  point P14 (460, -80.15)
  point P3 (460, 0)
  point P10 (460, -160)
  point P13 (460, -120.15)
  point P15 (444.8, -80.15)
  point P17 (460, -40.3)
  point P18 (0, -160)
  point P19 (15.2, -160)
  point P21 (0, -120.15)
  point P22 (0, -80.15)
  point P23 (15.2, -80.15)
  point P25 (0, -40.3)
  horizontal L1
  vertical L20
  vertical L23
  coincident P1 P2
  perpendicular L2 L23
  horizontal L6
  vertical L7
  horizontal L8
  horizontal L9
  vertical L10
  horizontal L11
  coincident P14 L20
  horizontal L12
  vertical L13
  horizontal L14
  horizontal L15
  vertical L16
  horizontal L17
  collinear L19 L20
  collinear L20 L21
  collinear L22 L23
  collinear L23 L24
  horizontal L25
  dimension "d1" distance P2 P3 = 460
  dimension "d10" distance P10 P13 = 39.85
  dimension "d11" distance P14 P15 = 15.2
  dimension "d12" distance P14 P17 = 39.85
  dimension "d13" distance P13 P14 = 40
  dimension "d14" distance P18 P19 = 15.2
  dimension "d15" distance P18 P21 = 39.85
  dimension "d16" distance P22 P23 = 15.2
  dimension "d17" distance P22 P25 = 39.85
extrude "Extrude1" new body sketch "Sketch1" profile of L1 L21 L24 L2 L3 L4 L5 L6 L7 L8 L9 L10 L11 L12 L13 L14 L15 L16 L17 L18 L25 along normal blind 15

design "lateralAdelante_projectfinal"
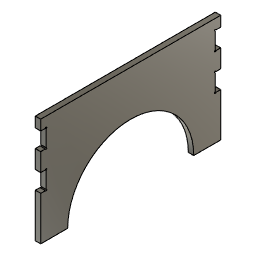
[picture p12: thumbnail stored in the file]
sketch "Sketch1" plane through (0, 0, 0) normal (1, 0, 0) x axis (0, 1, 0)
  line L1 (-31, -0.35) -> (469, -0.35)
  line L2 (469, -28.86) -> (469, -0.35)
  line L3 (455.8, -28.86) -> (469, -28.86)
  line L4 (453.8, -76.86) -> (453.8, -30.86)
  line L5 (469, -78.86) -> (455.8, -78.86)
  line L6 (455.8, -78.86) -> (469, -78.86)
  line L7 (469, -129.21) -> (455.8, -129.21)
  line L8 (455.8, -129.21) -> (469, -129.21)
  line L9 (453.8, -177.21) -> (453.8, -131.21)
  line L10 (455.8, -179.21) -> (469, -179.21)
  line L11 (-31.2, -178.86) -> (-18.0006, -178.86)
  line L12 (-18.0006, -128.86) -> (-31.2, -128.86)
  line L13 (-16.0006, -130.86) -> (-16.0006, -176.86)
  line L14 (-31.1702, -28.86) -> (-17.9434, -28.86)
  line L15 (-18, -78.51) -> (-31.2, -78.51)
  line L16 (-31.2, -78.51) -> (-18, -78.51)
  line L17 (-31.2, -128.86) -> (-18.0006, -128.86)
  line L18 (-16, -30.5098) -> (-16, -76.51)
  line L19 (469, -129.21) -> (469, -78.86)
  line L20 (469, -229.56) -> (469, -179.21)
  line L21 (469, -300.35) -> (469, -280.26)
  line L22 (-31, -300.35) -> (-31, -279.56)
  line L23 (-31, -229.21) -> (-31, -178.86)
  line L24 (-31, -28.86) -> (-31, -0.35)
  line L25 (-31, -128.86) -> (-31, -78.51)
  line L26 (44, -300.35) -> (-31, -300.35)
  line L27 (469, -300.35) -> (394, -300.35)
  line L28 (-31, -279.56) -> (-31, -229.21)
  line L29 (469, -280.26) -> (469, -229.56)
  arc A1 centre (219, -300.35) radius 175 clockwise from (44, -300.35) to (394, -300.35)
  arc A2 centre (-15.9742, -28.51) radius 2 clockwise from (-17.9434, -28.86) to (-16, -30.5098)
  arc A3 centre (-16, -78.51) radius 2 clockwise from (-16, -76.51) to (-18, -78.51)
  arc A4 centre (-16.0006, -128.86) radius 2 clockwise from (-18.0006, -128.86) to (-16.0006, -130.86)
  arc A5 centre (-16.0006, -178.86) radius 2 clockwise from (-16.0006, -176.86) to (-18.0006, -178.86)
  arc A6 centre (453.8, -28.86) radius 2 clockwise from (453.8, -30.86) to (455.8, -28.86)
  arc A7 centre (453.8, -78.86) radius 2 clockwise from (455.8, -78.86) to (453.8, -76.86)
  arc A8 centre (453.8, -129.21) radius 2 clockwise from (453.8, -131.21) to (455.8, -129.21)
  arc A9 centre (453.8, -179.21) radius 2 clockwise from (455.8, -179.21) to (453.8, -177.21)
  point P20 (-31, -128.86)
  point P21 (-31, -178.86)
  point P22 (-31, -28.86)
  point P23 (-31, -78.51)
  point P26 (394, -300.35)
  point P24 (219, -300.35)
  point P2 (469, -0.35)
  point P3 (-31, -0.35)
  point P5 (469, -300.35)
  point P6 (469, -28.86)
  point P39 (453.8, -28.86)
  point P7 (469, -78.86)
  point P40 (453.8, -78.86)
  point P8 (469, -129.21)
  point P9 (469, -179.21)
  point P16 (-31.1702, -28.86)
  point P27 (-15.9742, -28.51)
  point P28 (-16, -78.51)
  point P13 (-31.2, -78.51)
  point P33 (-16.0006, -128.86)
  point P34 (-16.0006, -178.86)
  horizontal L1
  vertical L24
  perpendicular L1 L2
  horizontal L3
  vertical L4
  horizontal L5
  horizontal L6
  horizontal L7
  horizontal L8
  vertical L9
  horizontal L10
  horizontal L14
  horizontal L15
  vertical L18
  horizontal L16
  horizontal L12
  horizontal L17
  vertical L13
  horizontal L11
  collinear L19 L20
  collinear L20 L21
  collinear L22 L24
  coincident L12 P20
  coincident L11 P21
  collinear L23 L24
  coincident L14 P22
  coincident L15 P23
  collinear L24 L25
  perpendicular L21 L26
  coincident P26 L26
  collinear L26 L27
  coincident P24 L26
  parallel L22 L28
  perpendicular L1 L29
  dimension "d1" distance P2 P3 = 500
  dimension "d2" distance P2 P5 = 300
  dimension "d4" distance P2 P6 = 28.51
  dimension "d5" distance P6 P39 = 15.2
  dimension "d6" distance P6 P7 = 50
  dimension "d7" distance P7 P40 = 15.2
  dimension "d8" distance P7 P8 = 50.35
  dimension "d10" distance P8 P9 = 50
  dimension "d16" distance P16 P27 = 15.2
  dimension "d17" distance P27 P28 = 50
  dimension "d18" distance P13 P28 = 15.2
  dimension "d19" distance P28 P33 = 50.35
  dimension "d20" distance P33 P34 = 50
  dimension "d25" diameter A1 = 350
  dimension "d30" diameter A2 = 4
  dimension "d31" diameter A3 = 4
  dimension "d32" diameter A4 = 4
  dimension "d33" diameter A5 = 4
  dimension "d34" diameter A6 = 4
  dimension "d35" diameter A7 = 4
  dimension "d36" diameter A8 = 4
  dimension "d37" diameter A9 = 4
  dimension "d38" distance P3 P16 = 28.51
  dimension "d26" alignAngle = 0
  dimension "d27" alignOffsetX = 0
  dimension "d28" alignOffsetY = 0
  dimension "d29" alignOffsetZ = 0
extrude "Extrude2" new body sketch "Sketch1" profile of L1 L25 L2 L3 L4 L5 L6 L7 L8 L9 L10 L11 L12 L13 L14 L15 L16 L17 L18 L21 L27 A1 L28 L29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 along normal blind 15

design "_dht22 aM2302.38a1238d-d74f-4ad3-8c3c-e908f9285f82"
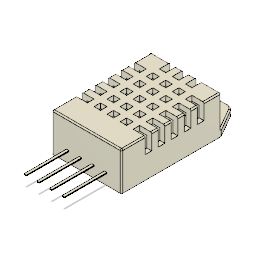
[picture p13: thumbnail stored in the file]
parameter "Hole" = 1.31
sketch "Sketch1" plane through (0, 0, 0) normal (0, 1, 0) x axis (1, 0, 0)
  dimension "d2" = 5.1
  dimension "d3" = 20
  dimension "d4" = 3.1
  dimension "d5" = 2.35
  dimension "d6" = 8.12 (= "( ( 2.04 * 3 ) * 1 mm ) + 2 mm")
  dimension "d7" = 0.5
  dimension "d8" = 0.5
  dimension "d10" = 0.5
  dimension "d11" = 8.5
  dimension "d12" = 2.04
  dimension "d13" = 2.04
  dimension "d14" = 0.5
  dimension "d15" = 2.54
extrude "Extrude1" new body sketch "Sketch1" along normal blind 7.7
extrude "Extrude2" add sketch "Sketch1" along normal blind 1.3
extrude "Extrude3" add sketch "Sketch1" along normal blind 2.3
extrude "Extrude4" cut sketch "Sketch1" along normal blind 2.1
fillet "Fillet1" radius 1.5
fillet "Fillet3" radius 0.25
fillet "Fillet4" radius 0.25
shell "Shell1" innerThickness 1
sketch "Sketch3" plane through (0, 7.7, 0) normal (0, 1, 0) x axis (-1, 0, 0)
  dimension "d29" = 1.31 (= "Hole")
  dimension "d31" = 1.31 (= "Hole")
  dimension "d33" = 1.31 (= "Hole")
  dimension "d34" = 1.31 (= "Hole")
  dimension "d35" = 1.31 (= "Hole")
  dimension "d36" = 1.31 (= "Hole")
  dimension "d37" = 1.31 (= "Hole")
  dimension "d38" = 1.31 (= "Hole")
  dimension "d39" = 1.31 (= "Hole")
  dimension "d40" = 1.31 (= "Hole")
  dimension "d41" = 1.31 (= "Hole")
  dimension "d42" = 1.31 (= "Hole")
  dimension "d43" = 1.31 (= "Hole")
  dimension "d44" = 1.31 (= "Hole")
  dimension "d45" = 1.31 (= "Hole")
  dimension "d46" = 1.31 (= "Hole")
  dimension "d53" = 17.2208
  dimension "d58" = 4.5
  dimension "d59" = 20
  dimension "d60" = 1.31 (= "Hole")
  dimension "d62" = 2.65
extrude "Extrude5" cut sketch "Sketch3" against normal blind 3.2
sketch "Sketch4" plane through (0, 0, 9) normal (0, 0, -1) x axis (-1, 0, 0)
extrude "Extrude6" add sketch "Sketch4" along normal blind 18
extrude "Extrude7" add of existing geometry to an object
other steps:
create_component "CreateComponent1"

design "LCD_grande"
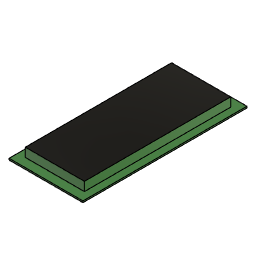
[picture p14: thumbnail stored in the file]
sketch "Boceto" plane through (0, 0, 0) normal (0, 0, 1) x axis (1, 0, 0)
  line L1 (-15.2, 69) -> (34.8, 69)
  line L2 (-15.2, -42) -> (-15.2, 69)
  line L3 (34.8, -42) -> (-15.2, -42)
  line L4 (34.8, 69) -> (34.8, -42)
  line L5 (-15.2, -42) -> (34.8, 69)
  line L6 (34.8, -42) -> (-15.2, 69)
  point P6 (9.8, 13.5)
  point P4 (-15.2, -42)
  point P5 (34.8, -42)
  point P3 (-15.2, 69)
  horizontal L1
  perpendicular L1 L2
  parallel L1 L3
  parallel L2 L4
  coincident L5 P6
  coincident L6 P6
  dimension "d9" distance P4 P5 = 50
  dimension "d10" distance P3 P4 = 111
  dimension "d5" AlongDistance = -1
  dimension "d6" TaperAngle = 0
  dimension "d7" AlongDistance = -0.3
  dimension "d8" TaperAngle = 0
extrude "Extruir" new body sketch "Boceto" profile of L1 L2 L3 L4 along normal blind 1
sketch "Sketch6" plane through (0, 0, 1) normal (0, 0, 1) x axis (-1, 0, 0)
  line L1 (-34.8, -69) -> (-34.8, 42)
  line L2 (15.2, -69) -> (-34.8, -69)
  line L3 (15.2, 42) -> (15.2, -69)
  line L4 (-34.8, 42) -> (15.2, 42)
  line L5 (-29.8, 36) -> (10.2, 36)
  line L6 (-29.8, -63) -> (-29.8, 36)
  line L7 (10.2, -63) -> (-29.8, -63)
  line L8 (10.2, 36) -> (10.2, -63)
  line L9 (-29.8, -63) -> (10.2, 36)
  line L10 (10.2, -63) -> (-29.8, 36)
  point P10 (-9.8, -13.5)
  point P8 (-29.8, -63)
  point P9 (10.2, -63)
  point P7 (-29.8, 36)
  horizontal L5
  perpendicular L5 L6
  parallel L5 L7
  parallel L6 L8
  coincident L9 P10
  coincident L10 P10
  dimension "d15" distance P8 P9 = 40
  dimension "d16" distance P7 P8 = 99
extrude "Extrude8" new body sketch "Sketch6" profile of L5 L6 L7 L8 along normal blind 6

design "lateralD_projectfinal"
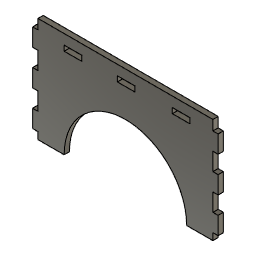
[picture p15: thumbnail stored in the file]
sketch "Sketch1" plane through (0, 0, 0) normal (0, 1, 0) x axis (1, 0, 0)
  line L1 (0, 0) -> (-500, 0)
  line L2 (-374.65, 28.51) -> (-425, 28.51)
  line L3 (-374.65, 43.71) -> (-374.65, 28.51)
  line L4 (-425, 43.71) -> (-374.65, 43.71)
  line L5 (-425, 28.51) -> (-425, 43.71)
  line L6 (-273.1255, 28.51) -> (-273.1255, 43.71)
  line L7 (-222.7755, 28.51) -> (-273.1255, 28.51)
  line L8 (-273.1255, 43.71) -> (-222.7755, 43.71)
  line L9 (-222.7755, 43.71) -> (-222.7755, 28.51)
  line L10 (-65.7396, 28.51) -> (-116.0896, 28.51)
  line L11 (-65.7396, 43.71) -> (-65.7396, 28.51)
  line L12 (-116.0896, 43.71) -> (-65.7396, 43.71)
  line L13 (-116.0896, 28.51) -> (-116.0896, 43.71)
  line L14 (-75, 300) -> (0, 300)
  line L15 (-500, 300) -> (-425, 300)
  line L16 (-500, 28.51) -> (-500, 0)
  line L17 (-515.2, 28.51) -> (-500, 28.51)
  line L18 (-515.2, 78.86) -> (-515.2, 28.51)
  line L19 (-515.2, 78.86) -> (-500, 78.86)
  line L20 (-500, 129.21) -> (-515.2, 129.21)
  line L21 (-500, 129.21) -> (-515.2, 129.21)
  line L22 (-515.2, 179.56) -> (-500, 179.56)
  line L23 (-515.2, 129.21) -> (-515.2, 179.56)
  line L24 (-500, 229.91) -> (-515.2, 229.91)
  line L25 (-515.2, 280.26) -> (-500, 280.26)
  line L26 (-515.2, 229.91) -> (-515.2, 280.26)
  line L27 (-0.2, 179.56) -> (15, 179.56)
  line L28 (15, 28.51) -> (15, 78.86)
  line L29 (-0.2, 78.86) -> (15, 78.86)
  line L30 (15, 129.21) -> (-0.2, 129.21)
  line L31 (15, 229.91) -> (-0.2, 229.91)
  line L32 (15, 280.26) -> (15, 229.91)
  line L33 (15, 129.21) -> (-0.2, 129.21)
  line L34 (-0.2, 28.51) -> (15, 28.51)
  line L35 (15, 179.56) -> (15, 129.21)
  line L36 (-0.2, 280.26) -> (15, 280.26)
  line L37 (-500, 0) -> (-500, 28.51)
  line L38 (-500, 78.86) -> (-500, 129.21)
  line L39 (0, 300) -> (0, 280.26)
  line L40 (0, 28.51) -> (0, 0)
  line L41 (-500, 280.26) -> (-500, 300)
  line L42 (-500, 179.56) -> (-500, 229.91)
  line L43 (0, 129.21) -> (0, 78.86)
  line L44 (0, 229.91) -> (0, 179.56)
  arc A1 centre (-250, 300) radius 175 clockwise from (-75, 300) to (-425, 300)
  point P6 (-250, 300)
  point P48 (0, 229.91)
  point P49 (0, 280.26)
  point P50 (0, 28.51)
  point P51 (0, 78.86)
  point P52 (0, 129.21)
  point P53 (0, 179.56)
  point P2 (-500, 0)
  point P5 (-500, 300)
  point P7 (-425, 28.51)
  point P8 (-374.65, 28.51)
  point P10 (-425, 43.71)
  point P11 (-273.1255, 28.51)
  point P12 (-222.7755, 28.51)
  point P14 (-273.1255, 43.71)
  point P15 (-116.0896, 28.51)
  point P16 (-65.7396, 28.51)
  point P18 (-116.0896, 43.71)
  point P21 (-500, 28.51)
  point P22 (-515.2, 28.51)
  point P24 (-500, 78.86)
  point P25 (-515.2, 78.86)
  point P27 (-500, 129.21)
  point P26 (-515.2, 129.21)
  point P30 (-515.2, 179.56)
  point P31 (-515.2, 229.91)
  point P32 (-500, 229.91)
  point P34 (-515.2, 280.26)
  horizontal L1
  vertical L40
  horizontal L14
  vertical L41
  horizontal L2
  vertical L3
  horizontal L4
  vertical L5
  horizontal L7
  vertical L9
  horizontal L8
  vertical L6
  horizontal L10
  vertical L11
  horizontal L12
  vertical L13
  collinear L14 L15
  coincident P6 L14
  perpendicular L1 L16
  horizontal L17
  vertical L18
  horizontal L19
  horizontal L20
  horizontal L21
  horizontal L22
  vertical L23
  horizontal L24
  horizontal L25
  vertical L26
  horizontal L34
  vertical L28
  horizontal L29
  horizontal L33
  horizontal L30
  vertical L35
  horizontal L27
  horizontal L31
  vertical L32
  horizontal L36
  collinear L37 L41
  collinear L38 L41
  coincident L31 P48
  coincident L36 P49
  collinear L39 L40
  coincident L34 P50
  coincident L29 P51
  collinear L40 L43
  collinear L41 L42
  coincident L30 P52
  coincident L27 P53
  collinear L43 L44
  dimension "d1" distance P2 P5 = 300
  dimension "d3" distance P7 P8 = 50.35
  dimension "d4" distance P7 P10 = 15.2
  dimension "d6" distance P11 P12 = 50.35
  dimension "d7" distance P11 P14 = 15.2
  dimension "d9" distance P15 P16 = 50.35
  dimension "d10" distance P15 P18 = 15.2
  dimension "d13" distance P2 P21 = 28.51
  dimension "d14" distance P21 P22 = 15.2
  dimension "d15" distance P21 P24 = 50.35
  dimension "d16" distance P24 P25 = 15.2
  dimension "d17" distance P24 P27 = 50.35
  dimension "d19" distance P26 P30 = 50.35
  dimension "d21" distance P30 P31 = 50.35
  dimension "d22" distance P31 P32 = 15.2
  dimension "d23" distance P31 P34 = 50.35
extrude "Extrude1" new body sketch "Sketch1" profile of L1 L44 L15 L42 A1 L2 L3 L4 L5 L6 L7 L8 L9 L10 L11 L12 L13 along normal blind 15

design "acentral_unido" references "a_medioLateralIZQ", "a_centro_atras", "a_centro_adelante_final"
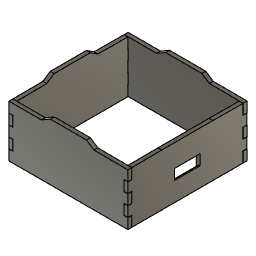
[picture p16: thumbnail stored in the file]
component_insert "Component Insert1"
component_insert "Component Insert2"
component_insert "Component Insert4"
component_insert "Component Insert5"

design "VENTILADOR"
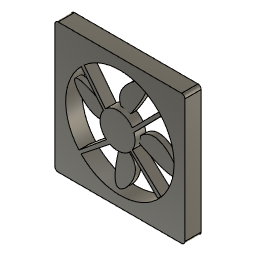
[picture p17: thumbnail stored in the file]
sketch "Sketch1" plane through (0, 0, 0) normal (0, 1, 0) x axis (1, 0, 0)
  line L1 (120, 0) -> (0, 0)
  line L2 (120, -120) -> (120, 0)
  line L3 (0, -120) -> (120, -120)
  line L4 (0, 0) -> (0, -120)
  point P1 (0, 0)
  point P2 (0, 0)
  point P3 (120, 0)
  point P5 (0, -120)
  horizontal L1
  vertical L2
  horizontal L3
  vertical L4
  coincident P1 P2
  dimension "d1" distance P2 P3 = 120
  dimension "d2" distance P2 P5 = 120
extrude "Extrude1" new body sketch "Sketch1" along normal blind 15
sketch "Sketch2" plane through (0, 0, 0) normal (0, -1, 0) x axis (1, 0, 0)
  line L1 (0, 120) -> (120, 120)
  line L2 (0, 0) -> (0, 120)
  line L3 (120, 0) -> (0, 0)
  line L4 (120, 120) -> (120, 0)
  circle C1 centre (60, 60) radius 50
  dimension "d5" diameter C1 = 100
extrude "Extrude2" cut sketch "Sketch2" profile of C1 distance 20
